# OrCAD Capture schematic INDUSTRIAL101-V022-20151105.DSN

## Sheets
1 01_Block_Diagram: title: Block Diagram; rev: 3.0; company: dog hunter Inc.; note: Freedog; note: 8F-4, No.17, Ln. 91, Sec. 1,; note: Neihu Rd., Neihu Dist., Taipei City
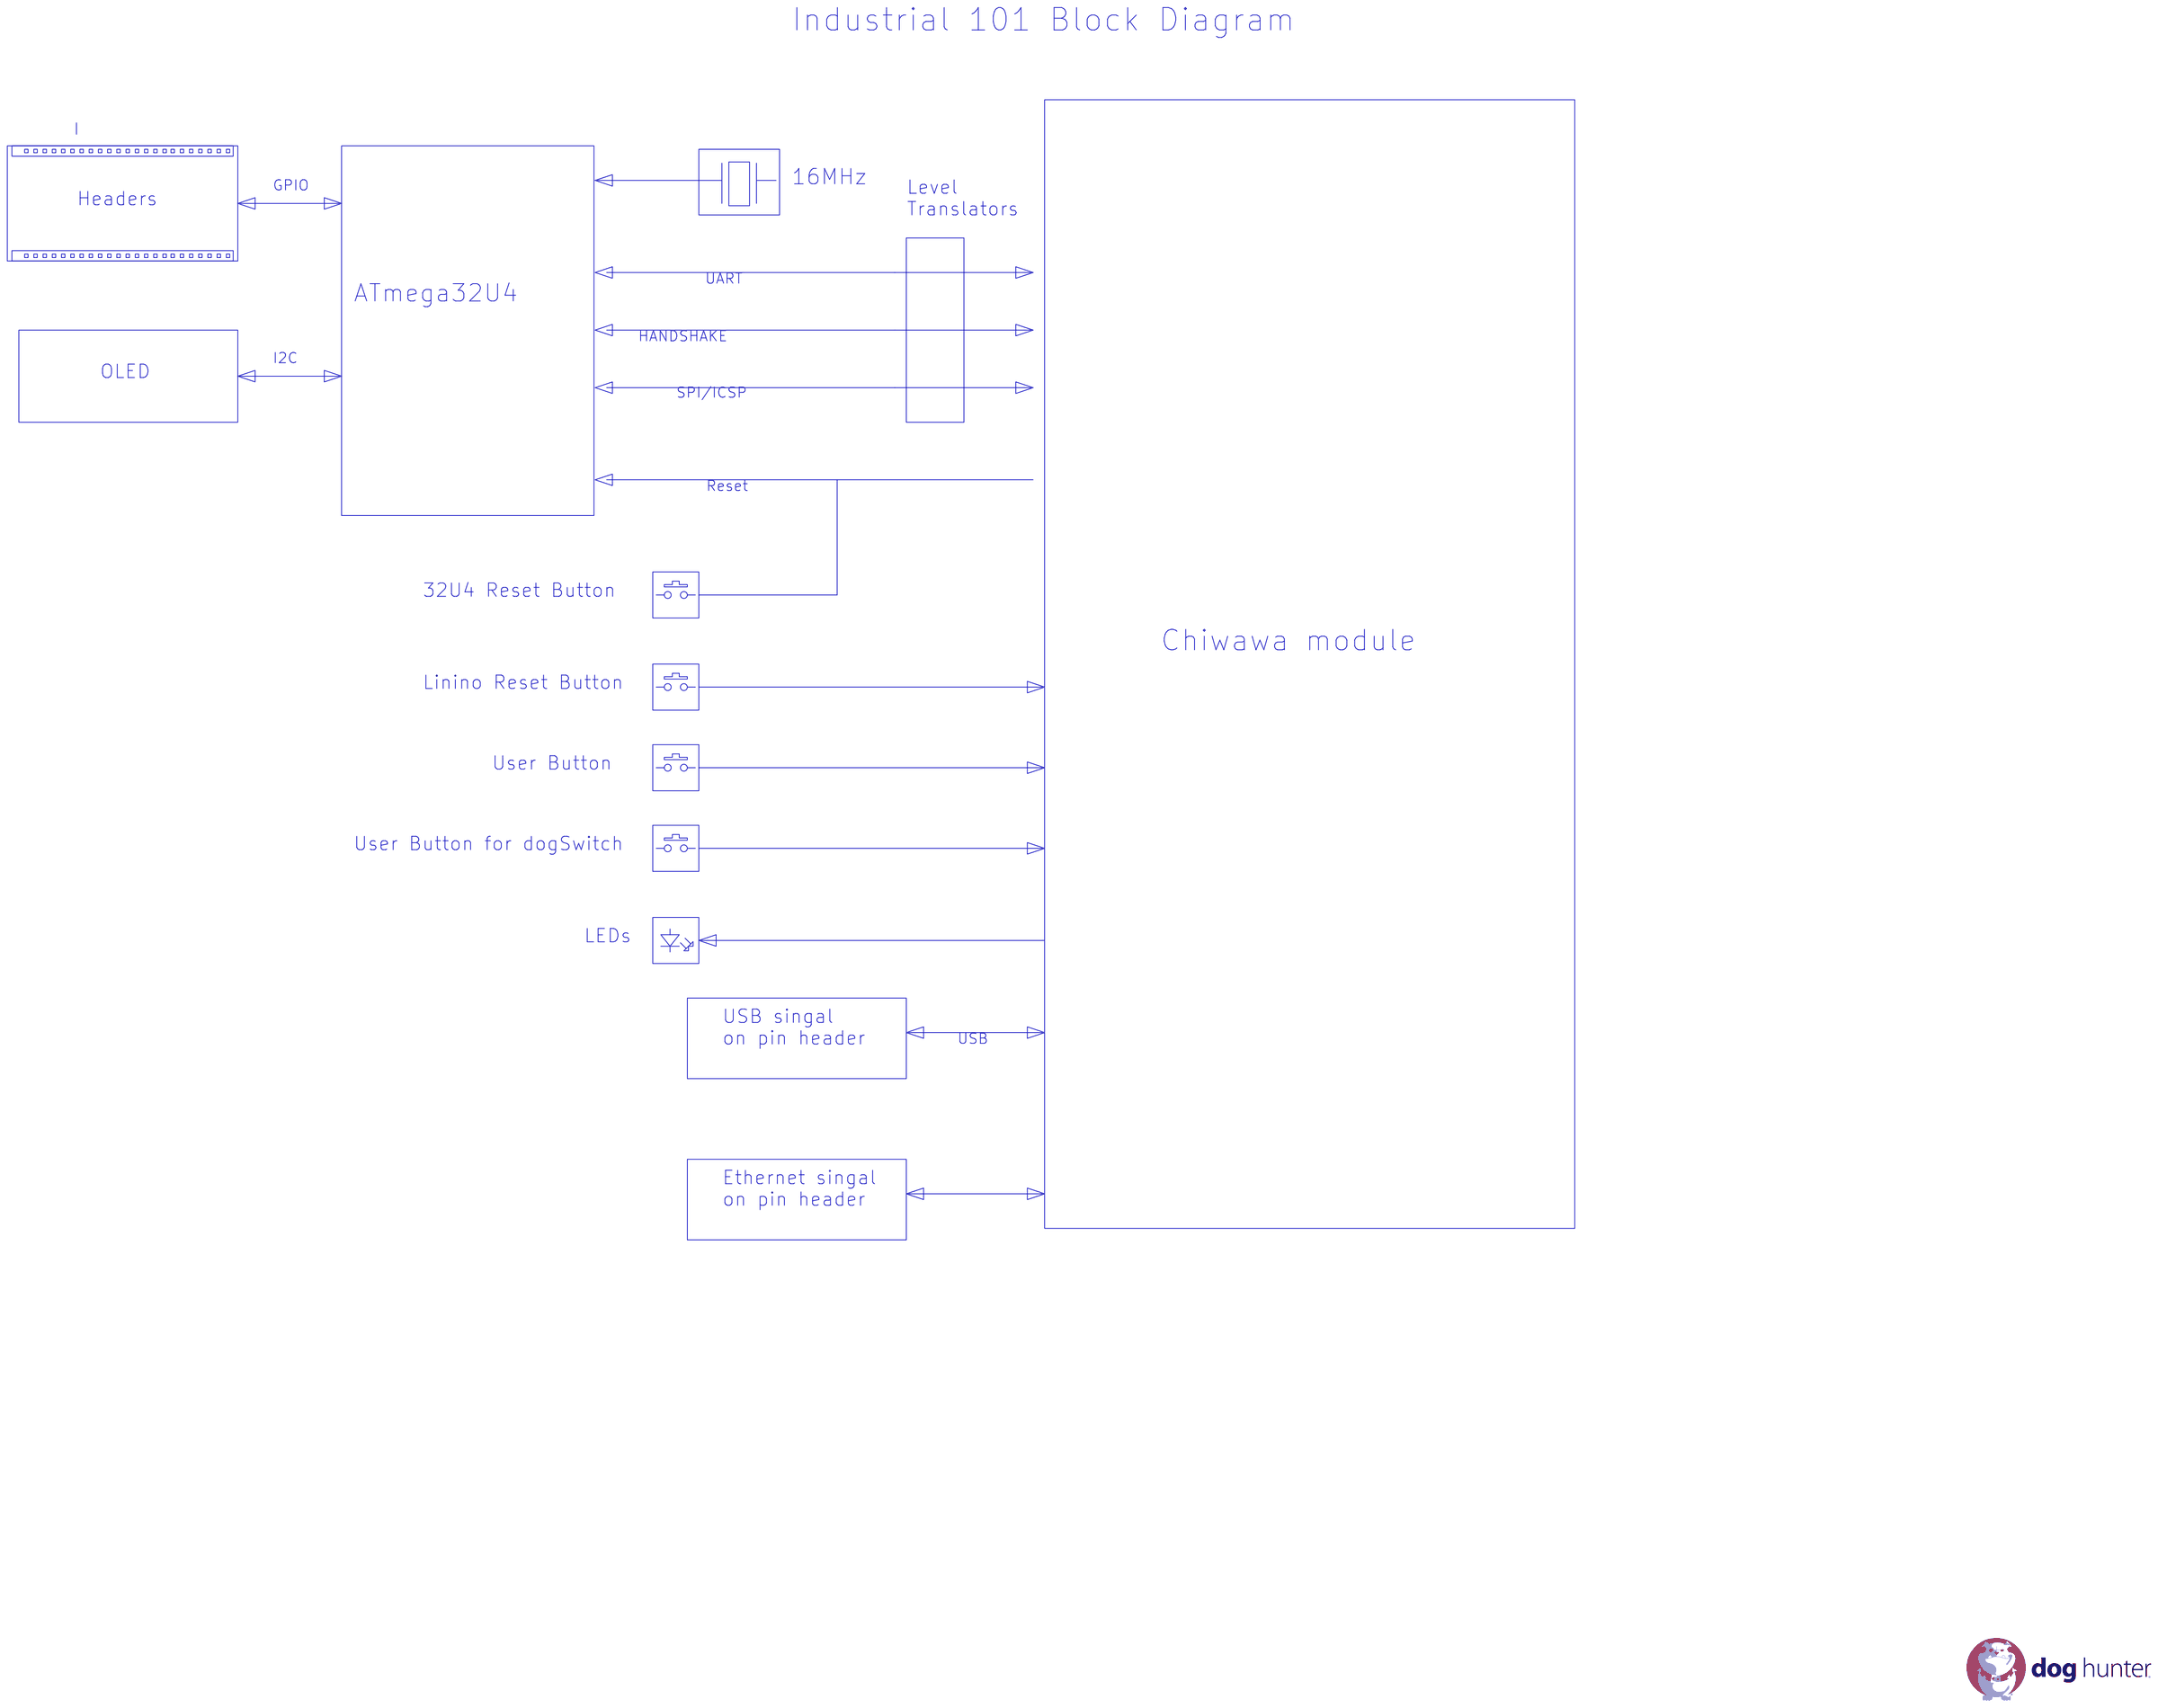
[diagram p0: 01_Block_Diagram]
2 03_ATmega 32U4: size A3; title: ATMEGA32U4
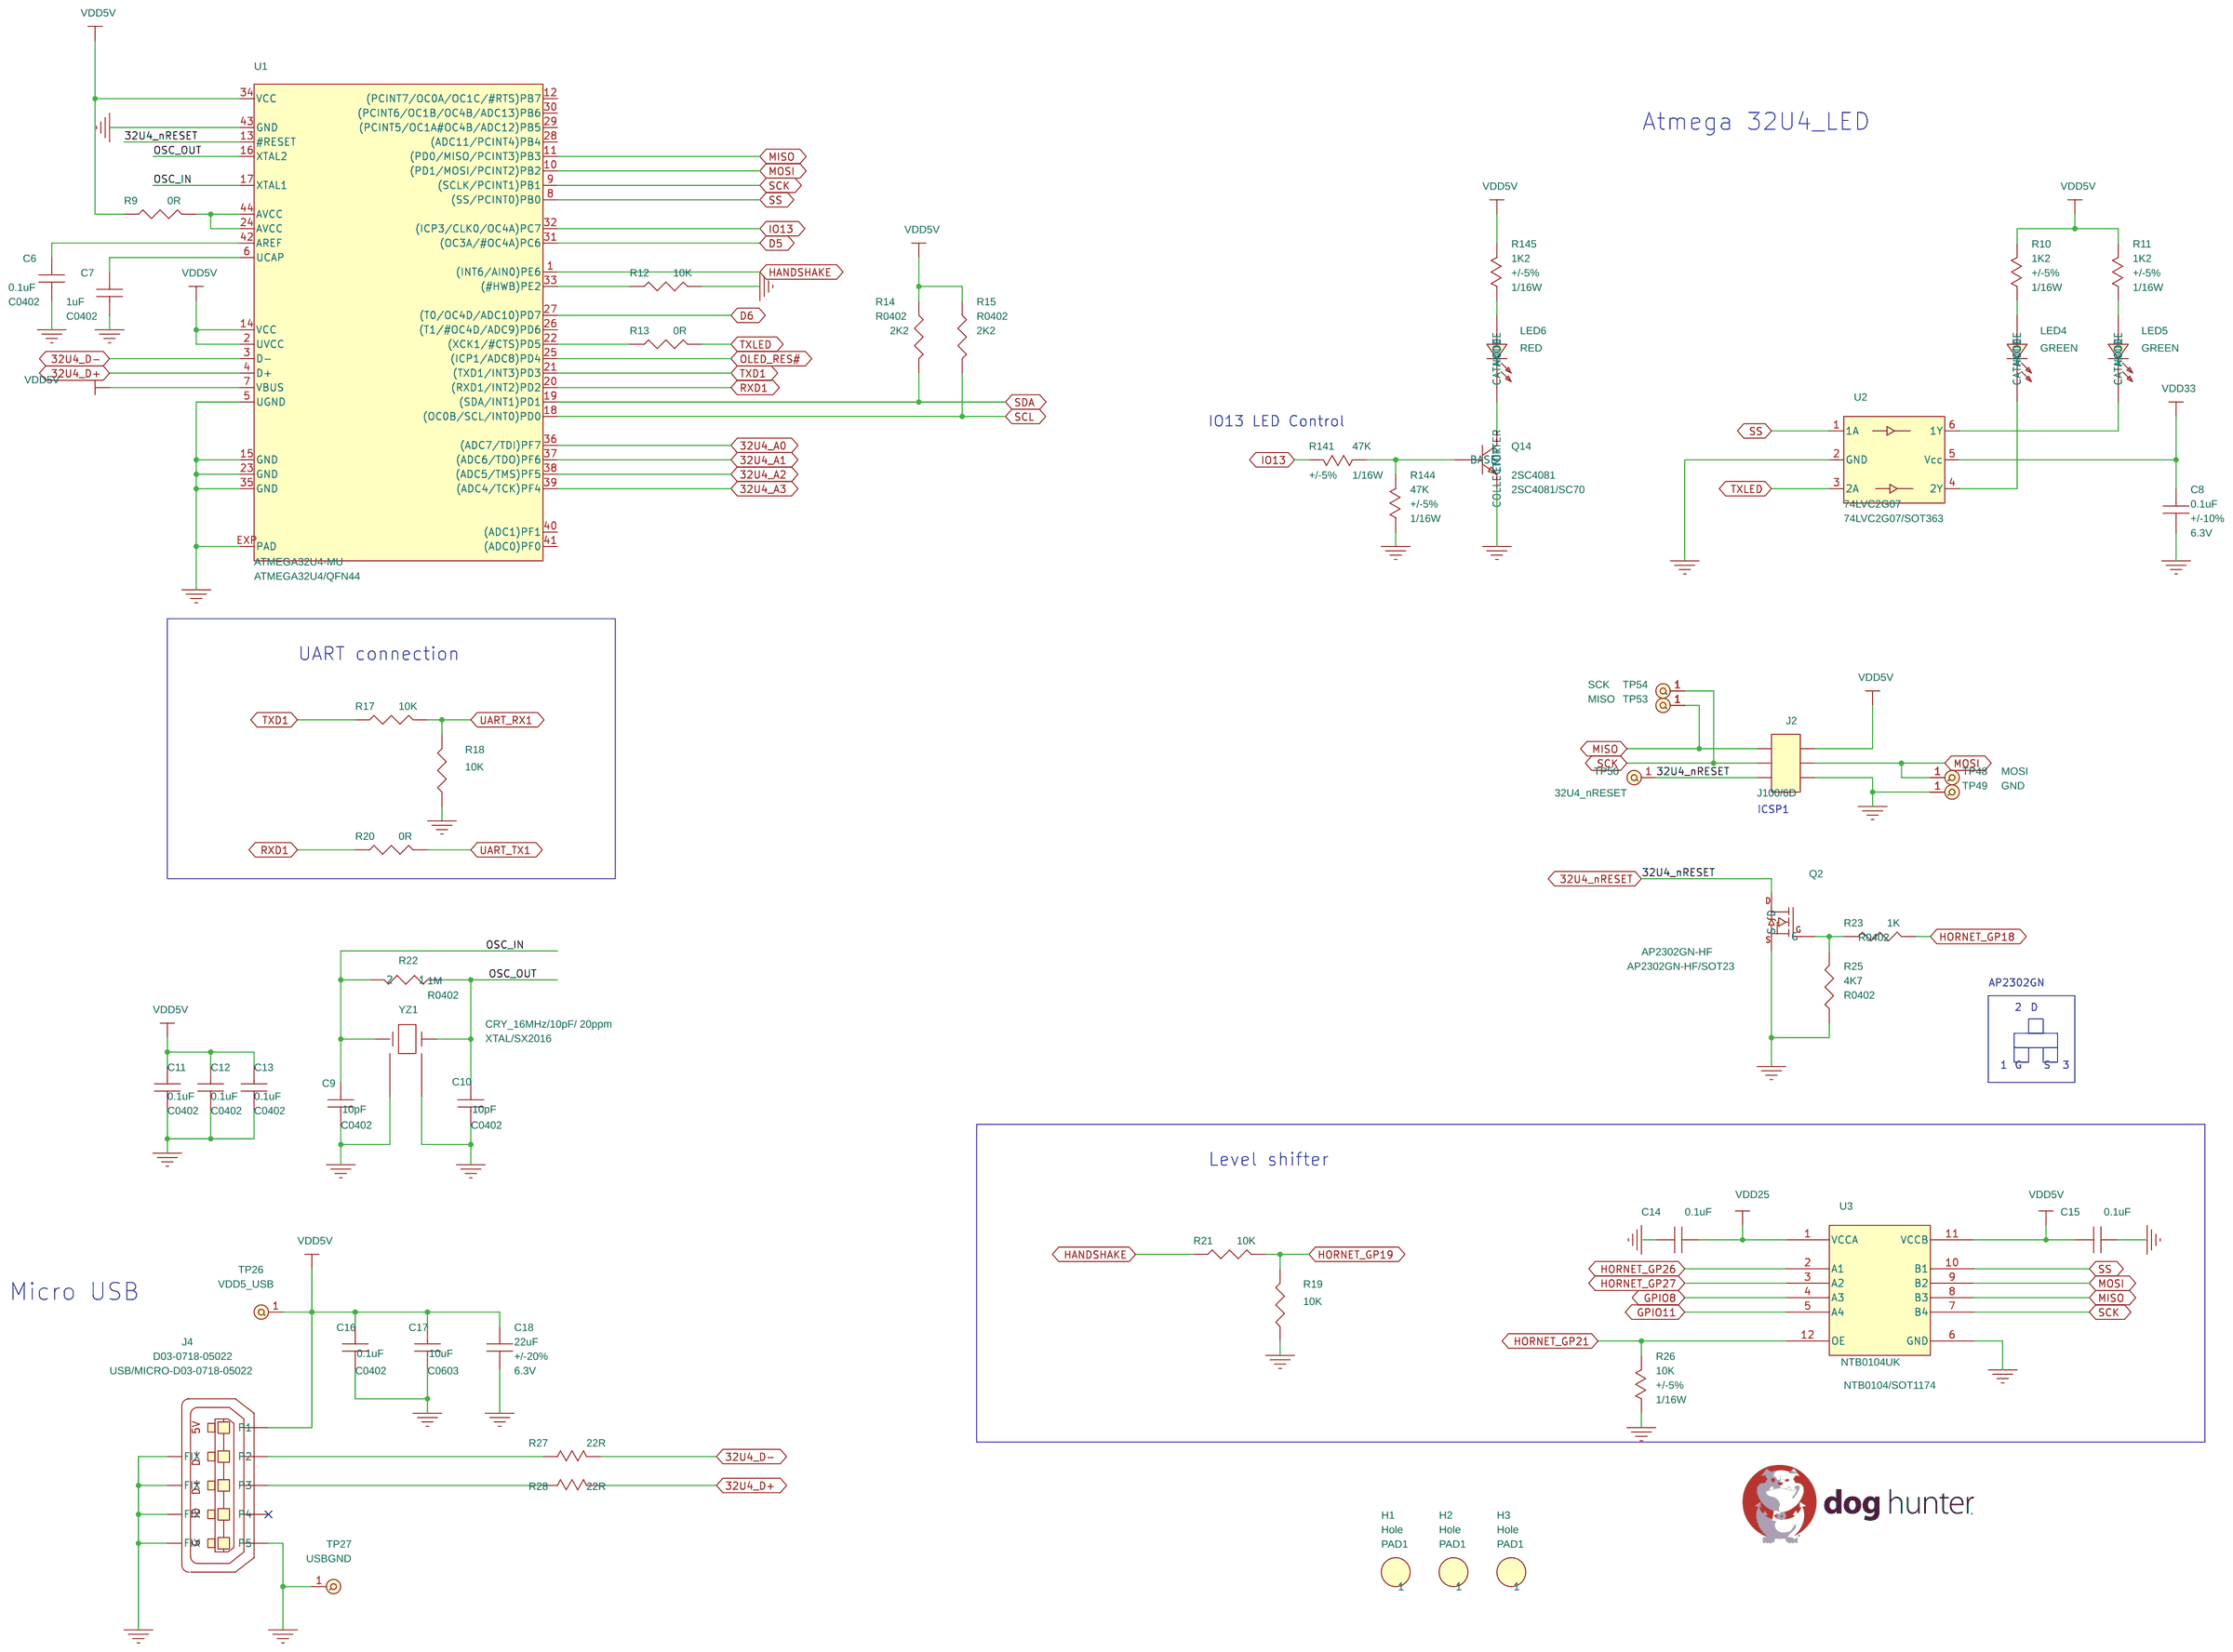
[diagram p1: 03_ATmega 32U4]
3 04_OLED/POWER: size A3; title: OLED
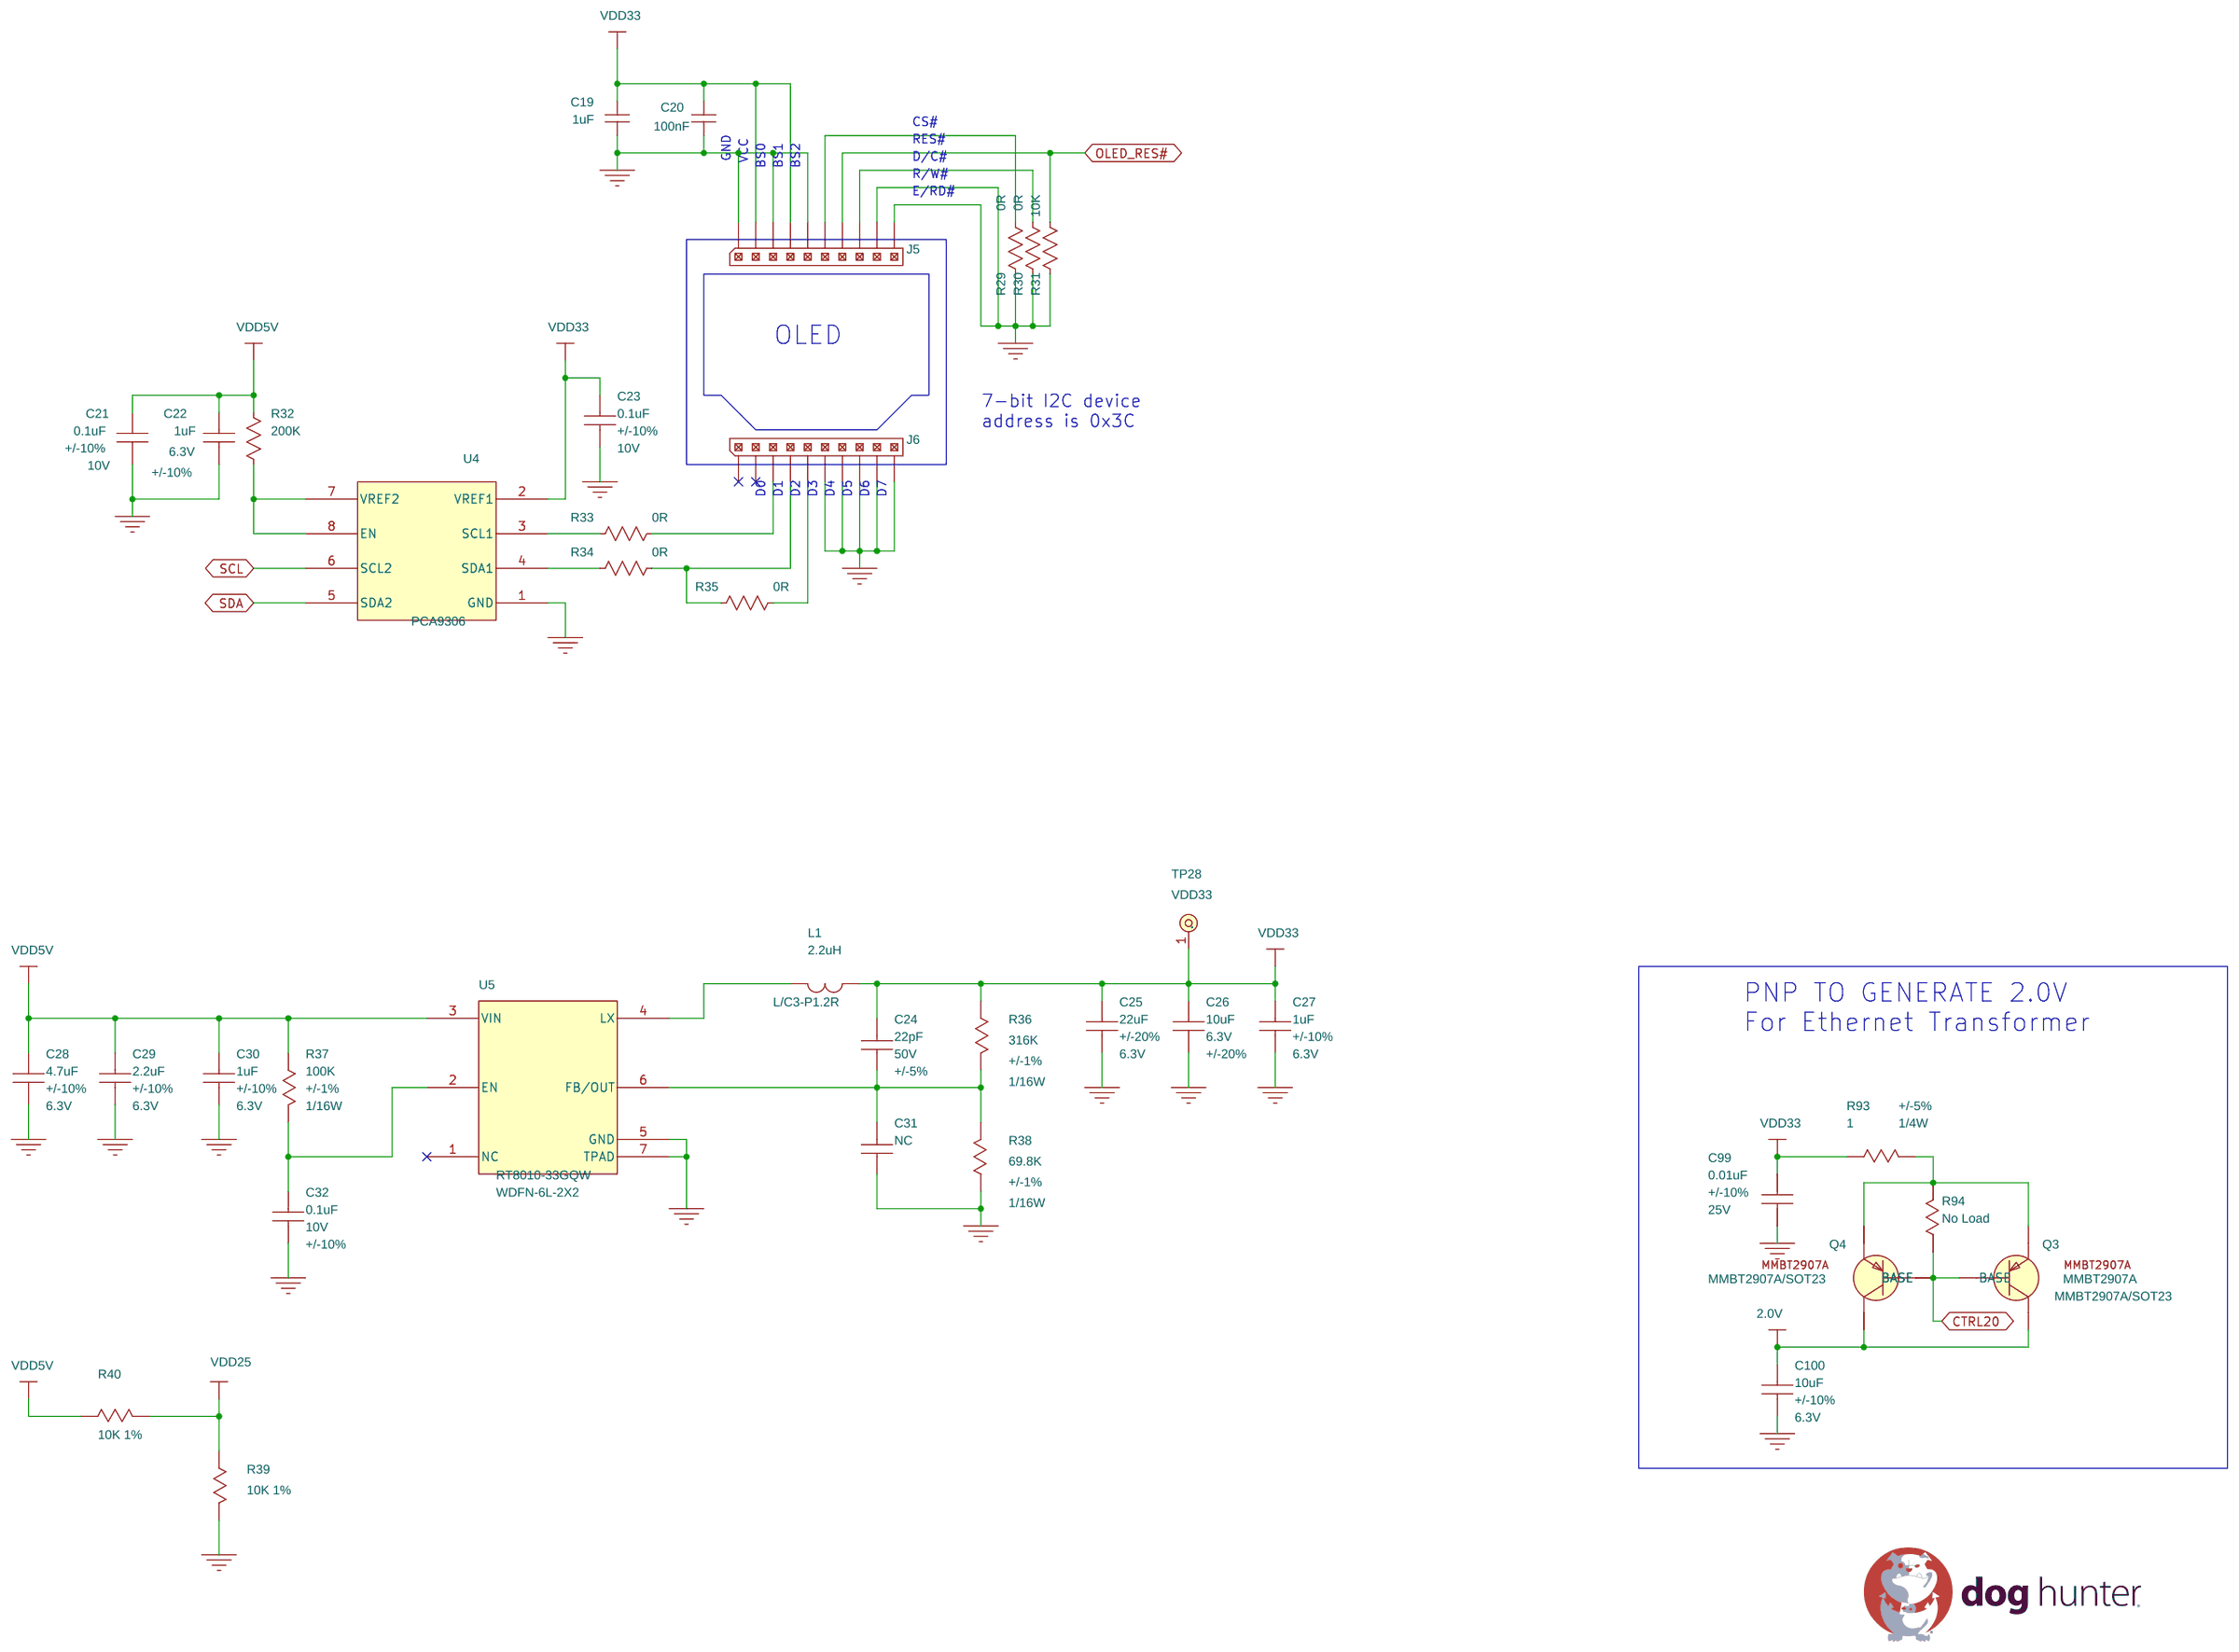
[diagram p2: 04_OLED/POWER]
4 02_WiFi Module/Buttons: size A3; title: Module Pin-Out
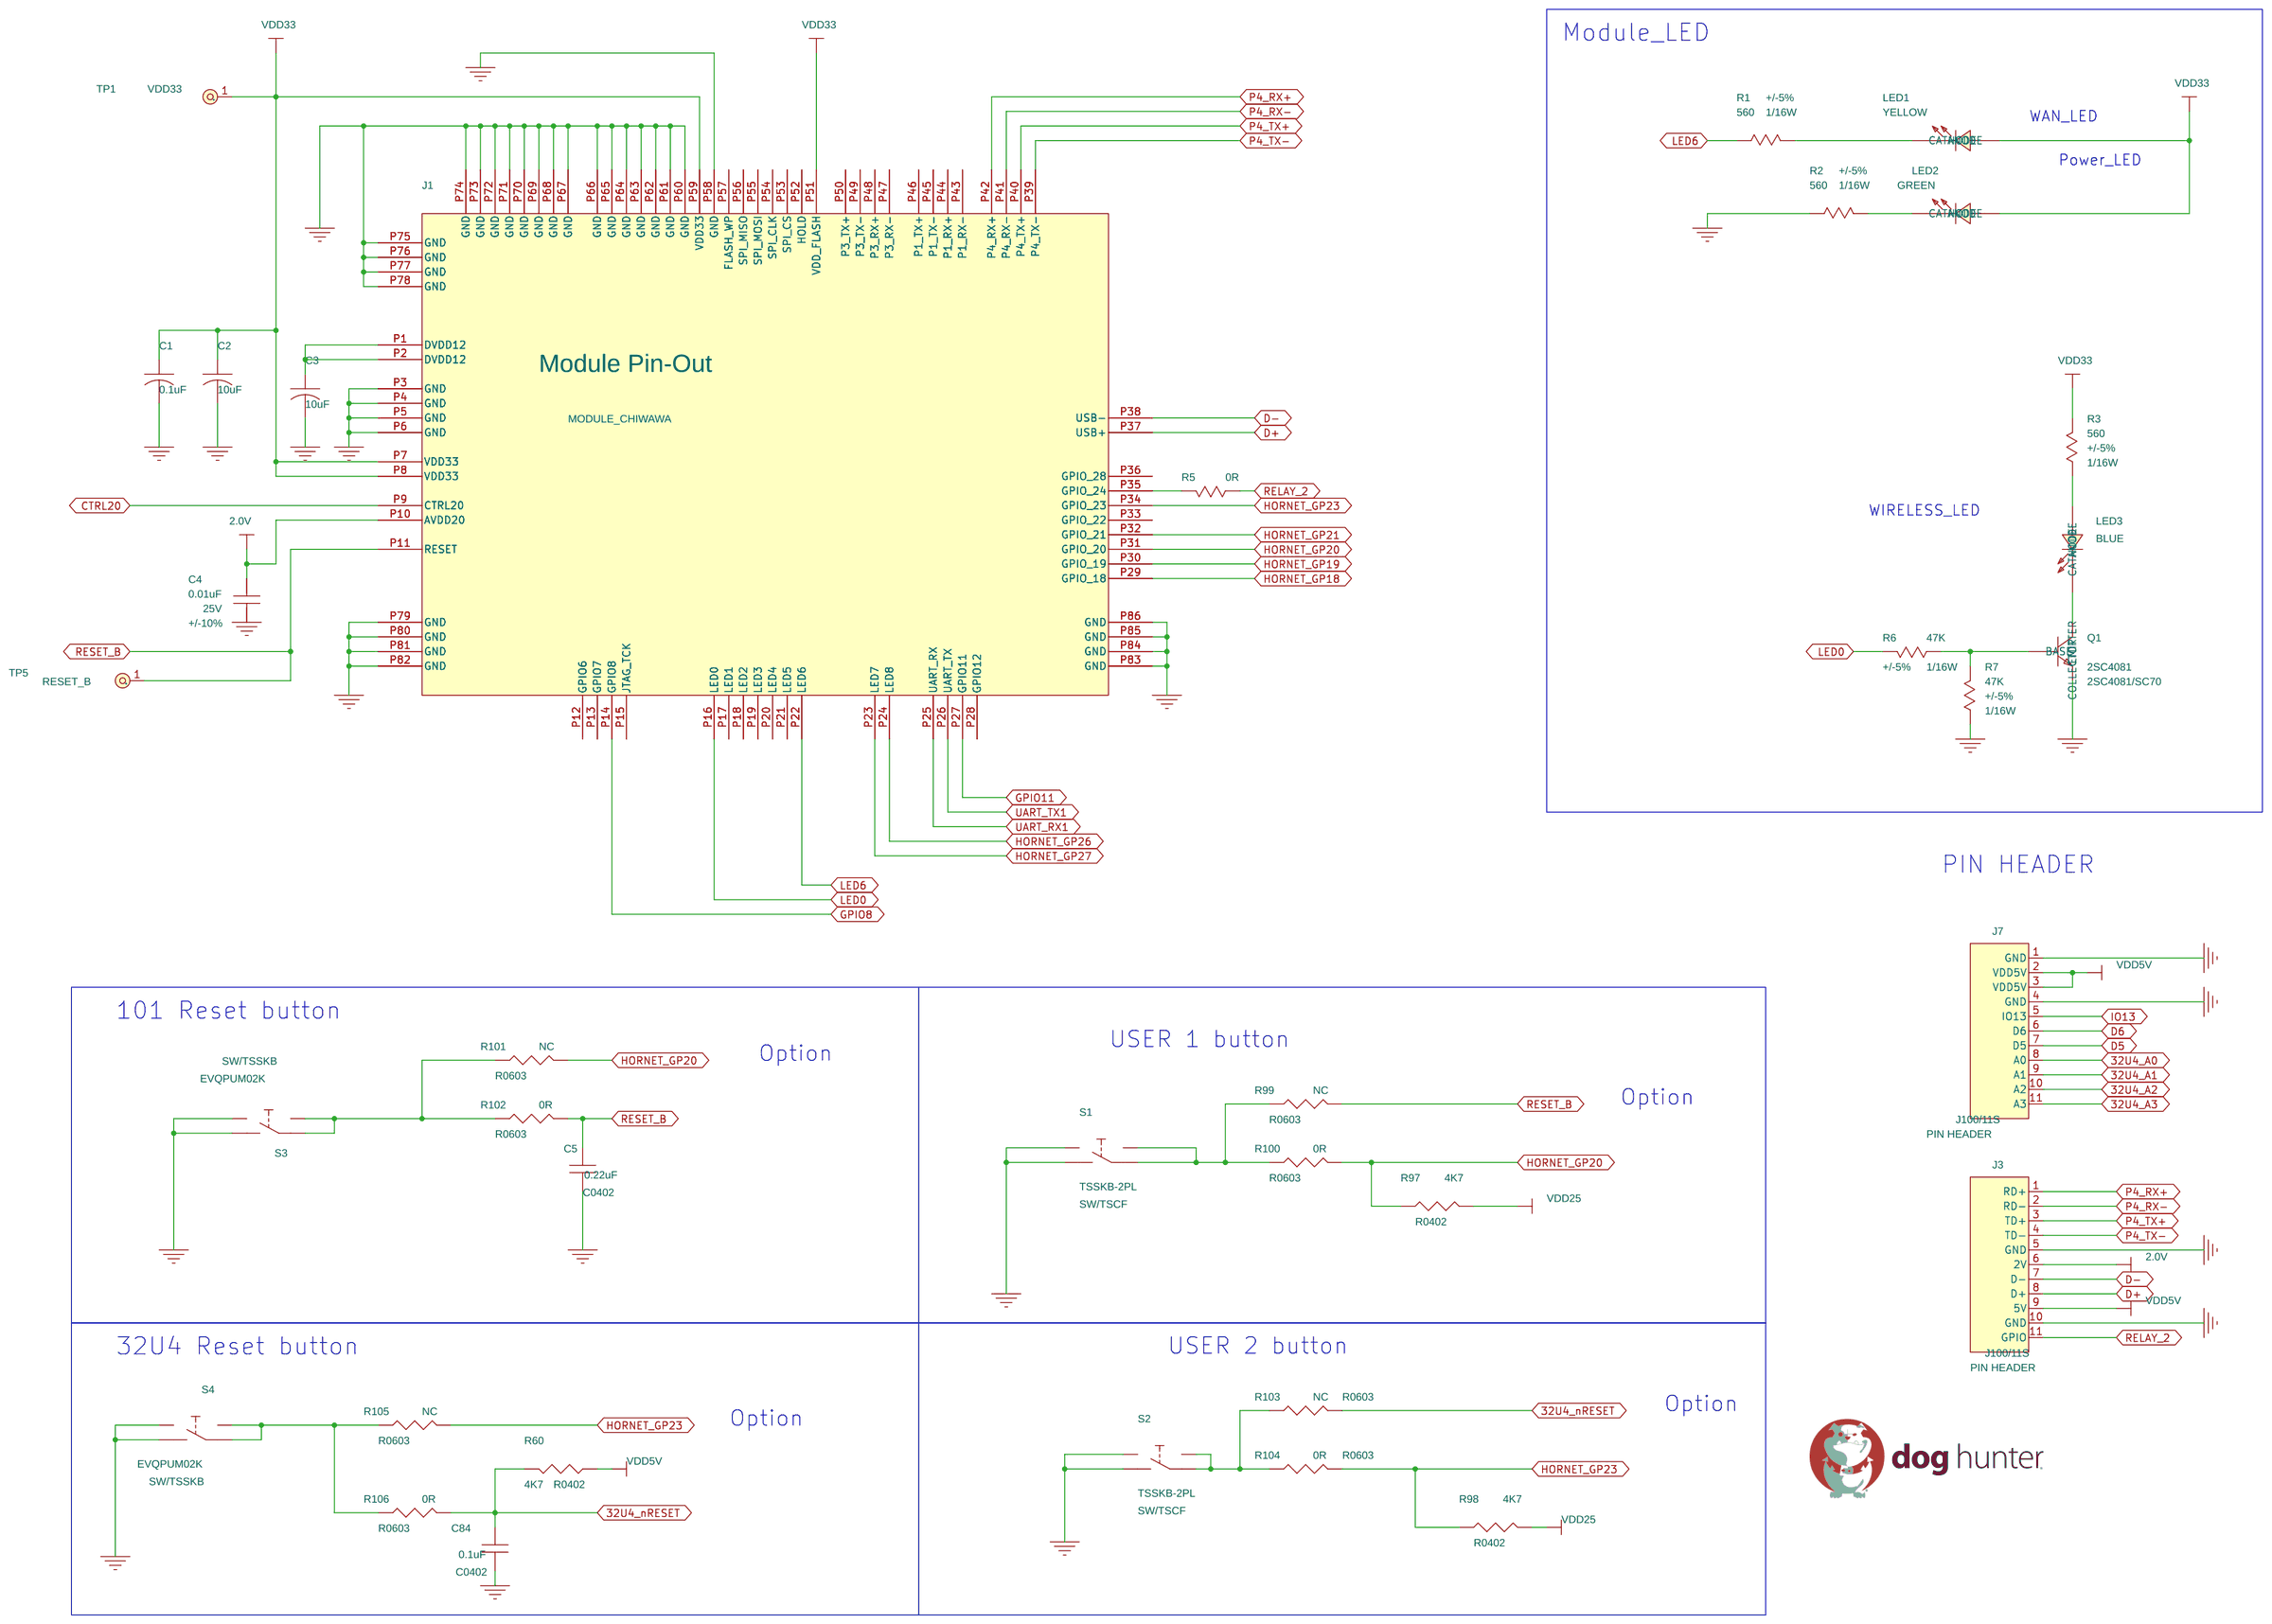
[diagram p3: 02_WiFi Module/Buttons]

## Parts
sheet 02_WiFi Module/Buttons
C1  0.1uF  [C0402]
C2  10uF  [C0603]
C3  10uF  [C0603]
C4  0.01uF  [C0402]
C5  0.22uF  [C0402]
C84  0.1uF  [C0402]
J1  Module Pin-Out  [MODULE_CHIWAWA]
J3  PIN HEADER  [J100/11S]
J7  PIN HEADER  [J100/11S]
LED1  YELLOW  [LED0603]
LED2  GREEN  [LED0603]
LED3  BLUE  [LED0603]
Q1  2SC4081  [2SC4081/SC70]
R1  560  [RES-0402]
R2  560  [RES-0402]
R3  560  [R0402]
R5  0R  [R0402]
R6  47K  [R0402]
R7  47K  [R0402]
R60  4K7  [R0402]
R97  4K7  [R0402]
R98  4K7  [R0402]
R99  NC  [R0603]
R100  0R  [R0603]
R101  NC  [R0603]
R102  0R  [R0603]
R103  NC  [R0603]
R104  0R  [R0603]
R105  NC  [R0603]
R106  0R  [R0603]
S1  TSSKB-2PL  [SW/TSCF]
S2  TSSKB-2PL  [SW/TSCF]
S3  EVQPUM02K  [SW/TSSKB]
S4  EVQPUM02K  [SW/TSSKB]
TP1  VDD33  [PADA]
TP5  RESET_B  [PADA]
sheet 03_ATmega 32U4
C6  0.1uF  [C0402]
C7  1uF  [C0402]
C8  0.1uF  [C0402]
C9  10pF  [C0402]
C10  10pF  [C0402]
C11  0.1uF  [C0402]
C12  0.1uF  [C0402]
C13  0.1uF  [C0402]
C14  0.1uF  [C0402]
C15  0.1uF  [C0402]
C16  0.1uF  [C0402]
C17  10uF  [C0603]
C18  22uF  [C0805]
H1  Hole  [PAD1]
H2  Hole  [PAD1]
H3  Hole  [PAD1]
J2  Pitch 2.54 mm  [J100/6D]
J4  MICRO_USB_5PIN_HORZ_SMD  [USB/MICRO-D03-0718-05022]
LED4  GREEN  [LED0603]
LED5  GREEN  [LED0603]
LED6  RED  [LED0603]
Q2  AP2302GN-HF  [AP2302GN-HF/SOT23]
Q14  2SC4081  [2SC4081/SC70]
R9  0R  [R0402]
R10  1K2  [R0402]
R11  1K2  [R0402]
R12  10K  [R0402]
R13  0R  [R0402]
R14  2K2  [R0402]
R15  2K2  [R0402]
R17  10K  [R0402]
R18  10K  [R0402]
R19  10K  [R0402]
R20  0R  [R0402]
R21  10K  [R0402]
R22  1M  [R0402]
R23  1K  [R0402]
R25  4K7  [R0402]
R26  10K  [R0402]
R27  22R  [R0402]
R28  22R  [R0402]
R141  47K  [R0402]
R144  47K  [R0402]
R145  1K2  [R0402]
TP26  VDD5_USB  [PADA]
TP27  USBGND  [PADA]
TP48  MOSI  [PADA]
TP49  GND  [PADA]
TP50  32U4_nRESET  [PADA]
TP53  MISO  [PADA]
TP54  SCK  [PADA]
U1  ATMEGA32U4-MU  [ATMEGA32U4/QFN44]
U2  74LVC2G07  [74LVC2G07/SOT363]
U3  NTB0104UK  [NTB0104/SOT1174]
YZ1  CRY_16MHz/10pF/ 20ppm  [XTAL/SX2016]
sheet 04_OLED/POWER
C19  1uF  [C0402]
C20  100nF  [C0402]
C21  0.1uF  [C0402]
C22  1uF  [C0402]
C23  0.1uF  [C0402]
C24  22pF  [C0402]
C25  22uF  [C0805]
C26  10uF  [C0603]
C27  1uF  [C0402]
C28  4.7uF  [C0603]
C29  2.2uF  [C0603]
C30  1uF  [C0402]
C31  NC  [C0402]
C32  0.1uF  [C0402]
C99  0.01uF  [C0402]
C100  10uF  [C0805]
J5  HEADER_2.54MM_VERT_PTH_10x1POS  [S216D-S-10-2-1B]
J6  HEADER_2.54MM_VERT_PTH_10x1POS  [S216D-S-10-2-1B]
L1  2.2uH  [L/C3-P1.2R]
Q3  MMBT2907A  [MMBT2907A/SOT23]
Q4  MMBT2907A  [MMBT2907A/SOT23]
R29  0R  [R0402]
R30  0R  [R0402]
R31  10K  [R0402]
R32  200K  [R0402]
R33  0R  [R0402]
R34  0R  [R0402]
R35  0R  [R0402]
R36  316K  [R0402]
R37  100K  [R0402]
R38  69.8K  [R0402]
R39  10K 1%  [R0402]
R40  10K 1%  [R0402]
R93  1  [R1206]
R94  No Load  [R0402]
TP28  VDD33  [PADA]
U4  PCA9306  [PCA9306/DCU]
U5  RT8010-33GQW  [WDFN-6L-2X2]

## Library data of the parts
C1-C3 = CAP_SM
C4 C99 = CAP: ATHEROS KEY: 031-103CK-004; AtherosDescription: CAP,0402,X7R,0.01uF,+/-10%,25V; CISPartType: Capacitor\0402; Tolerance: +/-10%; Voltage: 25V
C5 C9 C10 C16 C17 = 27PF_N_0402_5%
C6 C7 C11-C13 C84 = CAP_NP
J1 = Module_Pin-Out_35
J3 = HEADER_9_22
J7 = HEADER_9_23
LED1 = LED-0603-LTST-C190GKT_1: AtherosDescription: DIO,LED,GREEN CLEAR,0603,SMD; CISPartType: Diodes\LED
LED2 LED3 = LED-0603-LTST-C190GKT_0: AtherosDescription: DIO,LED,Yellow CLEAR,0603,SMD; CISPartType: Diodes\LED
Q1 Q14 = NPN_0: BJT NPN;50V;0.15A;SOT-323; Manufacturer: ROHM; yuhwei-footprint: SOT-323
R1 R2 = RES: ATHEROS KEY: 051-331RJ-000; AtherosDescription: RES,0402,330 OHMS,+/-5%,1/16W; CISPartType: Resistor\0402; PartType: Resistor\0402; StandardCost-100K: 0; Tolerance: +/-5%; URL: 1; VendorDescription: RES, 49R9, +/-1%, 1/16W, 0402, 7"T+R; VendorName: Yageo; VendorPart1: 517; VendorPartNumber: RC0402FR-0749R9L; WATTAGE: 1/16W
R3 R5-R7 R10 R11 R26 R141 R144 R145 = RES: ATHEROS KEY: 051-103RJ-000; AtherosDescription: RES,0402,10K OHMS,+/-5%,1/16W; CISPartType: Resistor\0402; Tolerance: +/-5%; WATTAGE: 1/16W
R19 R60 = R_4
R9 R97 = R_6
R15 R98 = R_7
R12 R99 = R
R21 R100 = R_10
R17 R101 = R_9
R18 R102 = R_3
R14 R103 = R_1
R25 R104 = R_8
R23 R105 = R_5
R20 R106 = R_2
S1 S2 = SW_PUSHBUTTON_4
S3 S4 = SW_PUSHBUTTON_2
TP1 TP5 TP26-TP28 TP48-TP50 TP53 TP54 = TP
C8 C14 C15 = CAP: ATHEROS KEY: 031-104CK-022; AtherosDescription: CAP,0402,X7R,0.1uF,+/-10%,10V; CISPartType: Capacitor\0402; Tolerance: +/-10%; Voltage: 6.3V
C18 C25 = CAP: ATHEROS KEY: 033-226CM-001; AtherosDescription: CAP,0805,X5R,22uF,+/-20%,6.3V; CISPartType: Capacitor\0805; Tolerance: +/-20%; Voltage: 6.3V
H1-H3 = PAD
J2 = CON7_6
J4 = USB_MINI_AB_RECEPTACLE_0: CONN MICRO USB; DESCR: D03-0718-05022; HEIGHT: 4.27MM; MFG_NAME01: TE Connectivity Ltd; MFG_PN01: 1734035-2; Part Type: USB/micro; ROHS: Yes
LED4-LED6 = LED-0603-LTST-C190GKT_0: AtherosDescription: DIO,LED,GREEN CLEAR,0603,SMD; CISPartType: Diodes\LED
Q2 = MOSFET_N_0
R13 = R_11
R22 = RESISTOR: Type: 5%
R27 R28 = RES: ATHEROS KEY: 051-000RJ-000; AtherosDescription: RES,0402,0 OHMS,+/-5%,1/16W; CISPartType: Resistor\0402; Tolerance: +/-5%; WATTAGE: 1/16W
U1 = 76160_5
U2 = NTB0104_6
U3 = NTB0104_4
YZ1 = CRY_SM_24MHz_4P_6
C19 = CAP_NP_v2: CAP CER 1UF 6.3V 10% X5R 0402; Package: 0402; Part Number: CAP_CER_1UF_6.3V_10%_X5R_0402; Part Type: Ceramic; Temp Coeff: X5R; Tolerance: 10%; Voltage: 6.3V
C20 = CAP_NP_v2: CAP CER 0.1UF 16V 10% X7R 0402; Package: 0402; Part Number: CAP_CER_0.1UF_16V_10%_X7R_0402; Part Type: Ceramic; Temp Coeff: X7R; Tolerance: 10%; Voltage: 16V
C21 C23 = CAP: ATHEROS KEY: 031-104CK-022; AtherosDescription: CAP,0402,X7R,0.1uF,+/-10%,10V; CISPartType: Capacitor\0402; Tolerance: +/-10%; Voltage: 10V
C22 = CAP: ATHEROS KEY: 031-105CK-000; AtherosDescription: CAP,0402,X5R,1uF, +/-10%,6.3V; CISPartType: Capacitor\0402; Tolerance: +/-10%; Voltage: 6.3V
C24 C31 = CAP: ATHEROS KEY: 031-332CK-000; AtherosDescription: CAP,0402,22pF,+/-5%,50V; CISPartType: Capacitor\0402; Tolerance: +/-5%; Voltage: 50V
C26 = CAP: ATHEROS KEY: 032-106CM-001; AtherosDescription: CAP,0603,X5R,10uF,+/-20%,6.3V; CISPartType: Capacitor\0603; StandardCost-100K: 0; Tolerance: +/-20%; URL: 0; VendorDescription: CAP, MLCC, X5R, 1uF +/-10%, 10V, 0603, 7"T+R; VendorName: Yageo; VendorPart1: 309; VendorPartNumber: CC0603KRX5R6BB105; Voltage: 6.3V
C27-C30 = CAP: ATHEROS KEY: 032-106CM-002; AtherosDescription: CAP,0603,X5R,10uF,+/-20%,10V; CISPartType: Capacitor\0603; Tolerance: +/-10%; Voltage: 6.3V
C32 = CAP: ATHEROS KEY: 031-104CK-022; AtherosDescription: CAP,0402,X7R,0.1uF,+/-10%,10V; CISPartType: Capacitor\0402; Tolerance: +/-10%; URL: 0; VendorDescription: equivalent of PHYCOMP / 04022F104M7B20D; VendorName: Yageo; VendorPart1: 662; Voltage: 10V
C100 = CAP: ATHEROS KEY: 033-106CK-001; AtherosDescription: CAP,0805,X5R,10uF,10%,6.3V; CISPartType: Capacitor\0805; Tolerance: +/-10%; Voltage: 6.3V
J5 J6 = RECEPT_10X1: CONN RCPT 10POS .100" PTH; Part Type: Header
L1 = IND_v2: ATHEROS KEY: 079-100LX-000; AtherosDescription: IND,Thru_Hole,10uH,+/-25%, COIL; CISPartType: Inductor\Thru_Hole; Tolerance: +/-25%
Q3 = TRA-SOT23-MMBT2907A_2: ATHEROS KEY: 130-00021-000; AtherosDescription: TRA,SOT-23,PNP General Purpose Amplifier; CISPartType: Transistors
Q4 = TRA-SOT23-MMBT2907A_2: AtherosDescription: TRA,SOT-23,PNP General Purpose Amplifier; CISPartType: Transistors
R29 = R_v2_3: RES 0.0 OHM 1/16W JUMP 0402 SMD; Package: 0402; Part Number: RES_0.0_OHM_1/16W_JUMP_0402_SMD; Part type: Thick film; Power: 1/16W; Tolerance: NA
R30 = R_v2_1: RES 0.0 OHM 1/16W JUMP 0402 SMD; Package: 0402; Part Number: RES_0.0_OHM_1/16W_JUMP_0402_SMD; Part type: Thick film; Power: 1/16W; Tolerance: NA
R31 = R_v2: RES 10K OHM 1/16W 1% 0402 SMD; Package: 0402; Part Number: RES_10K_OHM_1/16W_1%_0402_SMD; Part type: Thick film; Power: 1/16W; Tolerance: 1%
R32 = R_v2_5: RES 200K OHM 1/16W 1% 0402 SMD; Package: 0402; Part Number: RES_200K_OHM_1/16W_1%_0402_SMD; Part type: Thick film; Power: 1/16W; Tolerance: 1%
R33 = R_v2_4: RES 0.0 OHM 1/16W JUMP 0402 SMD; Package: 0402; Part Number: RES_0.0_OHM_1/16W_JUMP_0402_SMD; Part type: Thick film; Power: 1/16W; Tolerance: NA
R34 = R_v2_2: RES 0.0 OHM 1/16W JUMP 0402 SMD; Package: 0402; Part Number: RES_0.0_OHM_1/16W_JUMP_0402_SMD; Part type: Thick film; Power: 1/16W; Tolerance: NA
R35 = R_v2_6: RES 0.0 OHM 1/16W JUMP 0402 SMD; Package: 0402; Part Number: RES_0.0_OHM_1/16W_JUMP_0402_SMD; Part type: Thick film; Power: 1/16W; Tolerance: NA
R36 R39 R40 = RES: ATHEROS KEY: 051-7152F-000; AtherosDescription: RES,0402,71.5K OHMS,+/-1%,1/16W; CISPartType: Resistor\0402; Tolerance: +/-1%; WATTAGE: 1/16W
R37 = RES: ATHEROS KEY: 051-104RF-000; AtherosDescription: RES,0402,100K OHMS,+/-1%,1/16W; CISPartType: Resistor\0402; Tolerance: +/-1%; WATTAGE: 1/16W
R38 = RES: ATHEROS KEY: 051-223RF-000; AtherosDescription: RES,0402,22K OHMS, +/-1%,1/16W; CISPartType: Resistor\0402; Tolerance: +/-1%; WATTAGE: 1/16W
R93 = RES: ATHEROS KEY: 054-010RJ-000; AtherosDescription: RES,1206,1 OHM,+/-5%,1/4W; CISPartType: Resistor\1206; Tolerance: +/-5%; WATTAGE: 1/4W
R94 = RES: ATHEROS KEY: 051-XXXXX-000; AtherosDescription: NO_LOAD,RES,0402; CISPartType: Resistor\0402; VendorPart1: 170
U4 = PCA9306_3
U5 = RT8250_0: ATHEROS KEY: 170-00183-000; AtherosDescription: REG,RT8010A,1A; CISPartType: IC\Regulator

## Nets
2.0V: C4.1(Pin1) C100.Pin1 J1.P10(AVDD20) J3.6(2V) Q3.C Q4.C
GND: C1.2 C2.2 C3.2 C4.2(Pin2) C5.2 C6.2 C7.2 C8.2(Pin2) C9.2 C10.2 C11.2 C12.2 C13.2 C14.2(Pin2) C15.1(Pin1) C16.2 C17.2 C18.Pin2 C19.1 C20.1 C21.2(Pin2) C22.2(Pin2) C23.2(Pin2) C25.Pin2 C26.2(Pin2) C27.Pin2 C28.Pin2 C29.Pin2 C30.Pin2 C31.1(Pin1) C32.Pin2 C84.2 C99.2(Pin2) C100.Pin2 J1.P3(GND) J1.P4(GND) J1.P5(GND) J1.P6(GND) J1.P58(GND) J1.P60(GND) J1.P61(GND) J1.P62(GND) J1.P63(GND) J1.P64(GND) J1.P65(GND) J1.P66(GND) J1.P67(GND) J1.P68(GND) J1.P69(GND) J1.P70(GND) J1.P71(GND) J1.P72(GND) J1.P73(GND) J1.P74(GND) J1.P75(GND) J1.P76(GND) J1.P77(GND) J1.P78(GND) J1.P79(GND) J1.P80(GND) J1.P81(GND) J1.P82(GND) J1.P83(GND) J1.P84(GND) J1.P85(GND) J1.P86(GND) J2.6 J3.5(GND) J3.10(GND) J4.5(P5) J4.6(FIX) J4.7(FIX) J4.8(FIX) J4.9(FIX) J5.1 J5.3 J5.5 J5.9 J5.10 J6.6 J6.7 J6.8 J6.9 J6.10 J7.1(GND) J7.4(GND) Q1.1(EMITTER) Q2.3(S) Q14.1(EMITTER) R2.2 R7.1 R12.2 R18.1 R19.1 R25.1 R26.1 R29.1 R30.1 R31.1 R38.1 R39.2 R144.1 S1.2 S1.4 S2.2 S2.4 S3.3 S3.4 S4.3 S4.4 TP27.1(.) TP49.1(.) U1.5(UGND) U1.15(GND) U1.23(GND) U1.35(GND) U1.43(GND) U1.EXP(PAD) U2.2(GND) U3.6(GND) U4.1(GND) U5.5(GND) U5.7(TPAD) YZ1.2 YZ1.4
VDD5V: C11.1 C12.1 C13.1 C15.2(Pin2) C16.1 C17.1 C18.Pin1 C21.1(Pin1) C22.1(Pin1) C28.Pin1 C29.Pin1 C30.Pin1 J2.2 J3.9(5V) J4.1(P1) J7.2(VDD5V) J7.3(VDD5V) R9.1 R10.2 R11.2 R14.1 R15.1 R32.2 R37.1 R40.1 R60.2 R145.2 TP26.1(.) U1.2(UVCC) U1.7(VBUS) U1.14(VCC) U1.34(VCC) U3.11(VCCB) U5.3(VIN)
VDD25: C14.1(Pin1) R39.1 R40.2 R97.2 R98.2 U3.1(VCCA)
VDD33: C1.1 C2.1 C8.1(Pin1) C19.2 C20.2 C23.1(Pin1) C24.2(Pin2) C25.Pin1 C26.1(Pin1) C27.Pin1 C99.1(Pin1) J1.P7(VDD33) J1.P8(VDD33) J1.P51(VDD_FLASH) J1.P59(VDD33) J5.2 J5.4 L1.1 LED1.1(ANODE) LED2.1(ANODE) R3.2 R36.1 R93.1 TP1.1(.) TP28.1(.) U2.5(Vcc) U4.2(VREF1)
32U4_A0: J7.8(A0) U1.36((ADC7/TDI)PF7)
32U4_A1: J7.9(A1) U1.37((ADC6/TDO)PF6)
32U4_A2: J7.10(A2) U1.38((ADC5/TMS)PF5)
32U4_A3: J7.11(A3) U1.39((ADC4/TCK)PF4)
32U4_D+: R28.2 U1.4(D+)
32U4_D-: R27.2 U1.3(D-)
32U4_nRESET: C84.1 J2.5 Q2.2(D) R60.1 R103.2 R106.2 TP50.1(.) U1.13(#RESET)
CTRL20: J1.P9(CTRL20) Q3.B(BASE) Q4.B(BASE) R94.1
D5: J7.7(D5) U1.31((OC3A/#OC4A)PC6)
D6: J7.6(D6) U1.27((T0/OC4D/ADC10)PD7)
D+: J1.P37(USB+) J3.8(D+)
D-: J1.P38(USB-) J3.7(D-)
GPIO8: J1.P14(GPIO8) U3.4(A3)
GPIO11: J1.P27(GPIO11) U3.5(A4)
HANDSHAKE: R21.1 U1.1((INT6/AIN0)PE6)
HORNET_GP18: J1.P29(GPIO_18) R23.2
HORNET_GP19: J1.P30(GPIO_19) R19.2 R21.2
HORNET_GP20: J1.P31(GPIO_20) R97.1 R100.2 R101.2
HORNET_GP21: J1.P32(GPIO_21) R26.2 U3.12(OE)
HORNET_GP23: J1.P34(GPIO_23) R98.1 R104.2 R105.2
HORNET_GP26: J1.P24(LED8) U3.2(A1)
HORNET_GP27: J1.P23(LED7) U3.3(A2)
IO13: J7.5(IO13) R141.2 U1.32((ICP3/CLK0/OC4A)PC7)
LED0: J1.P16(LED0) R6.2
LED6: J1.P22(LED6) R1.2
MISO: J2.1 TP53.1(.) U1.11((PD0/MISO/PCINT3)PB3) U3.8(B3)
MOSI: J2.4 TP48.1(.) U1.10((PD1/MOSI/PCINT2)PB2) U3.9(B2)
OLED_RES#: J5.7 R31.2 U1.25((ICP1/ADC8)PD4)
OSC_IN: C9.1 R22.2 U1.17(XTAL1) YZ1.1
OSC_OUT: C10.1 R22.1 U1.16(XTAL2) YZ1.3
P4_RX+: J1.P42(P4_RX+) J3.1(RD+)
P4_RX-: J1.P41(P4_RX-) J3.2(RD-)
P4_TX+: J1.P40(P4_TX+) J3.3(TD+)
P4_TX-: J1.P39(P4_TX-) J3.4(TD-)
RELAY_2: J3.11(GPIO) R5.1
RESET_B: C5.1 J1.P11(RESET) R99.2 R102.2 TP5.1(.)
RXD1: R20.1 U1.20((RXD1/INT2)PD2)
SCK: J2.3 TP54.1(.) U1.9((SCLK/PCINT1)PB1) U3.7(B4)
SCL: R15.2 U1.18((OC0B/SCL/INT0)PD0) U4.6(SCL2)
SDA: R14.2 U1.19((SDA/INT1)PD1) U4.5(SDA2)
SS: U1.8((SS/PCINT0)PB0) U2.1(1A) U3.10(B1)
TXD1: R17.1 U1.21((TXD1/INT3)PD3)
TXLED: R13.2 U2.3(2A)
UART_RX1: J1.P25(UART_RX) R17.2 R18.2
UART_TX1: J1.P26(UART_TX) R20.2
N29432891: C3.1 J1.P1(DVDD12) J1.P2(DVDD12)
N29510033: R99.1 R100.1 S1.1 S1.3
N29524367: LED3.1(ANODE) R3.1
N29524369: LED3.2(CATHODE) Q1.3(COLLECTOR)
N29524393: Q1.2(BASE) R6.1 R7.2
N29542028: R12.1 U1.33((#HWB)PE2)
N29542074: C6.1 U1.42(AREF)
N29542090: R9.2 U1.24(AVCC) U1.44(AVCC)
N29542274: C7.1 U1.6(UCAP)
N29551749: J4.2(P2) R27.1
N29551752: J4.3(P3) R28.1
N29555841: J5.8 R30.2
N29555853: J6.3 R33.2
N29555858: J6.4 R34.2 R35.1
N29555860: J6.5 R35.2
N29555862: J5.6 R29.2
N29558287: LED1.2(CATHODE) R1.1
N29558317: LED2.2(CATHODE) R2.1
N29559742: R13.1 U1.22((XCK1/#CTS)PD5)
N29564016: C32.Pin1 R37.2 U5.2(EN)
N29564066: C24.1(Pin1) C31.2(Pin2) R36.2 R38.2 U5.6(FB/OUT)
N29564241: L1.2 U5.4(LX)
N29566879: Q2.1(G) R23.1 R25.2
N29568677: LED5.1(ANODE) R11.1
N29568679: LED4.1(ANODE) R10.1
N29568689: LED4.2(CATHODE) U2.4(2Y)
N29568691: LED5.2(CATHODE) U2.6(1Y)
N29572263: R33.1 U4.3(SCL1)
N29572266: R34.1 U4.4(SDA1)
N29572757: R32.1 U4.7(VREF2) U4.8(EN)
N29573589: J1.P35(GPIO_24) R5.2
N29579769: R101.1 R102.1 S3.1 S3.2
N29589651: R103.1 R104.1 S2.1 S2.3
N29603777: Q3.E Q4.E R93.2 R94.2
N29618329: R105.1 R106.1 S4.1 S4.2
N29620022: Q14.2(BASE) R141.1 R144.2
N29620040: LED6.2(CATHODE) Q14.3(COLLECTOR)
N29620072: LED6.1(ANODE) R145.1

Not connected (* = marked no-connect by the designer): H1 1; H2 1; H3 1; J1 P12(GPIO6) P13(GPIO7) P15(JTAG_TCK) P17(LED1) P18(LED2) P19(LED3) P20(LED4) P21(LED5) P28(GPIO12) P33(GPIO_22) P36(GPIO_28) P43(P1_RX-) P44(P1_RX+) P45(P1_TX-) P46(P1_TX+) P47(P3_RX-) P48(P3_RX+) P49(P3_TX-) P50(P3_TX+) P52(HOLD) P53(SPI_CS) P54(SPI_CLK) P55(SPI_MOSI) P56(SPI_MISO) P57(FLASH_WP); J4 4(P4)*; J6 1* 2*; U1 12((PCINT7/OC0A/OC1C/#RTS)PB7) 26((T1/#OC4D/ADC9)PD6) 28((ADC11/PCINT4)PB4) 29((PCINT5/OC1A#OC4B/ADC12)PB5) 30((PCINT6/OC1B/OC4B/ADC13)PB6) 40((ADC1)PF1) 41((ADC0)PF0); U5 1(NC)*

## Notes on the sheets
sheet 1
- Industrial 101 Block Diagram
- GPIO
- 16MHz
- Level
  Translators
- Headers
- UART
- ATmega32U4
- HANDSHAKE
- I2C
- OLED
- SPI/ICSP
- Reset
- 32U4 Reset Button
- Chiwawa module
- Linino Reset Button
- User Button
- User Button for dogSwitch
- LEDs
- USB singal
  on pin header
- USB
- Ethernet singal
  on pin header
sheet 2
- Atmega 32U4_LED
- IO13 LED Control
- UART connection
- ICSP1
- AP2302GN
- 2
- D
- 1
- G
- S
- 3
- Level shifter
- Micro USB
sheet 3
- CS#
- RES#
- GND
- VCC
- D/C#
- BS0
- BS1
- BS2
- E/RD#
- R/W#
- OLED
- 7-bit I2C device
  address is 0x3C
- D0
- D1
- D2
- D3
- D4
- D5
- D6
- D7
- PNP TO GENERATE 2.0V
  For Ethernet Transformer
sheet 4
- Module_LED
- WAN_LED
- Power_LED
- WIRELESS_LED
- PIN HEADER
- 101 Reset button
- USER 1 button
- Option
- Option
- 32U4 Reset button
- USER 2 button
- Option
- Option
